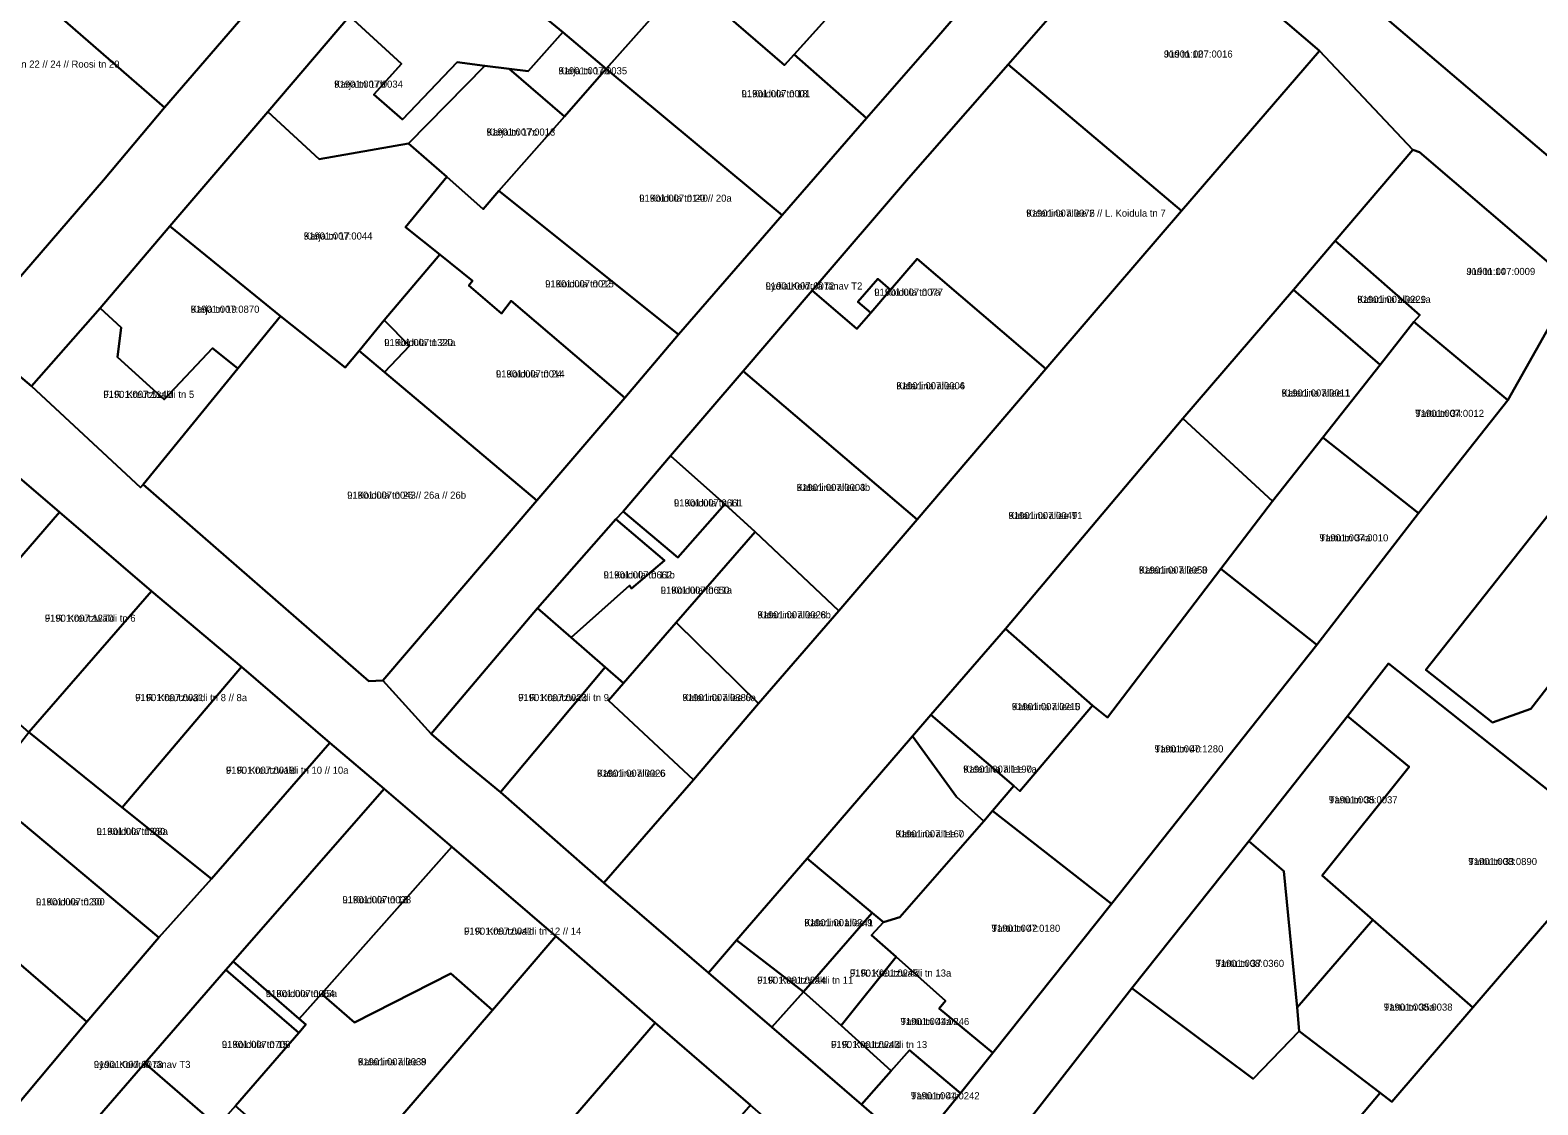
# Model space of a CAD drawing. Extents: x 675810 to 681273, y 6411190 to 6417565.
# Drawn here: x 677508.4 to 677826.5, y 6415551.1 to 6415777.9 of the extents above; entities that cross this region are included whole.
import ezdxf

# ---------------------------------------------------------------- set-up
doc = ezdxf.new("R2010")
doc.units = 0
for name, color, linetype in [('L_AADRESS', 7, 'Continuous'), ('PIIR', 7, 'Continuous'), ('TUNNUS', 7, 'Continuous')]:
    doc.layers.add(name, color=color, linetype=linetype)

msp = doc.modelspace()

# ---------------------------------------------------------------- linework, layer by layer
at = {"layer": 'PIIR'}
for points in [[(677646.67, 6415889.89), (677659.83, 6415878.49), (677628.13, 6415843.17), (677613.21, 6415825.66), (677592.59, 6415800.61), (677575.76, 6415780.87), (677558.51, 6415760.71), (677537.84, 6415736.57), (677523.1, 6415719.23), (677508.64, 6415702.82), (677495.67, 6415713.67), (677523.83, 6415746.25), (677536.7, 6415761.6), (677555.07, 6415782.89), (677568.57, 6415798.61), (677583.48, 6415815.98), (677590, 6415823.63), (677603.42, 6415839.6), (677616.31, 6415854.28)], [(677658.44, 6415802.86), (677696.86, 6415845.88), (677718.61, 6415827.15), (677669.55, 6415772.79), (677667.55, 6415770.56), (677646.64, 6415788.62), (677650.4, 6415793.16)], [(677827.43, 6415846.52), (677892.68, 6415798.34), (677892.37, 6415795.81), (677850.92, 6415745.75), (677846.94, 6415742.89), (677843.93, 6415741.95), (677839.54, 6415742.61), (677837.71, 6415743.69), (677790.48, 6415783.86), (677803.31, 6415799.07), (677793.83, 6415807.03)], [(677444.1, 6415758.98), (677420.94, 6415779.32), (677432.33, 6415792.43), (677449.54, 6415811.25), (677463.15, 6415826.36), (677481.9, 6415810.15), (677495.98, 6415797.3), (677514.66, 6415780.78), (677536.7, 6415761.6), (677523.83, 6415746.25), (677495.67, 6415713.67), (677477.14, 6415729.95)], [(677718.61, 6415827.15), (677732.71, 6415814.72), (677699.58, 6415776.22), (677684.86, 6415759.35), (677669.55, 6415772.79)], [(677613.21, 6415825.66), (677631.28, 6415809.88), (677650.4, 6415793.16), (677646.64, 6415788.62), (677629.89, 6415769.77), (677620.79, 6415777.53), (677592.59, 6415800.61)], [(677732.71, 6415814.72), (677744.3, 6415804.51), (677714.73, 6415770.67), (677693.73, 6415746.66), (677673.39, 6415722.95), (677658.8, 6415705.94), (677643.5, 6415688.11), (677633.48, 6415676.35), (677631.91, 6415674.7), (677615.44, 6415655.94), (677592.98, 6415629.43), (677582.81, 6415640.69), (677615.26, 6415678.66), (677633.81, 6415700.36), (677645.17, 6415713.67), (677667.03, 6415738.91), (677684.86, 6415759.35), (677699.58, 6415776.22)], [(677744.3, 6415804.51), (677780.41, 6415773.57), (677751.34, 6415739.78), (677714.73, 6415770.67)], [(677514.66, 6415780.78), (677533.83, 6415802.03), (677536.07, 6415800.01), (677555.07, 6415782.89), (677536.7, 6415761.6)], [(677586.72, 6415770.83), (677575.76, 6415780.87), (677592.59, 6415800.61), (677620.79, 6415777.53), (677613.42, 6415769.26), (677609.45, 6415769.75), (677604.33, 6415770.42), (677598.43, 6415771.15), (677586.9, 6415759.06), (677580.87, 6415764.37)], [(677646.64, 6415788.62), (677667.55, 6415770.56), (677669.55, 6415772.79), (677684.86, 6415759.35), (677667.03, 6415738.91), (677629.89, 6415769.77)], [(677575.76, 6415780.87), (677586.72, 6415770.83), (677580.87, 6415764.37), (677586.9, 6415759.06), (677598.43, 6415771.15), (677604.32, 6415770.43), (677588.2, 6415754.01), (677569.31, 6415750.71), (677558.51, 6415760.71)], [(677620.79, 6415777.53), (677629.89, 6415769.77), (677621.12, 6415759.72), (677609.43, 6415769.78), (677613.42, 6415769.26)], [(677751.34, 6415739.78), (677780.41, 6415773.57), (677800.15, 6415752.64), (677783.74, 6415733.44), (677774.92, 6415723.13), (677751.61, 6415695.94), (677714.14, 6415651.54), (677698.44, 6415633.45), (677694.58, 6415628.9), (677672.33, 6415603.11), (677657.41, 6415585.86), (677651.47, 6415579), (677629.42, 6415597.96), (677648.3, 6415619.73), (677662.03, 6415635.78), (677678.99, 6415655.4), (677695.52, 6415674.63), (677722.7, 6415706.45), (677732.45, 6415717.82)], [(677604.32, 6415770.43), (677609.43, 6415769.78), (677621.12, 6415759.72), (677607.26, 6415744.01), (677603.97, 6415740.16), (677596.26, 6415746.95), (677588.2, 6415754.01)], [(677629.89, 6415769.77), (677667.03, 6415738.91), (677645.17, 6415713.67), (677607.26, 6415744.01), (677621.12, 6415759.72)], [(677714.73, 6415770.67), (677751.34, 6415739.78), (677732.45, 6415717.82), (677722.7, 6415706.45), (677695.52, 6415729.64), (677689.93, 6415723.12), (677687.2, 6415725.47), (677683.03, 6415720.61), (677685.76, 6415718.27), (677682.83, 6415714.86), (677673.39, 6415722.95), (677693.73, 6415746.66)], [(677558.51, 6415760.71), (677569.31, 6415750.71), (677588.2, 6415754.01), (677596.26, 6415746.95), (677587.54, 6415736.38), (677594.79, 6415730.6), (677583.05, 6415716.73), (677577.75, 6415710.28), (677574.83, 6415706.76), (677561.2, 6415717.56), (677537.84, 6415736.57)], [(677800.15, 6415752.64), (677801.5, 6415752.2), (677830.81, 6415727.16), (677831.96, 6415720.82), (677820.17, 6415699.87), (677800.36, 6415716.35), (677801.58, 6415717.8), (677783.74, 6415733.44)], [(677596.26, 6415746.95), (677603.97, 6415740.16), (677607.26, 6415744.01), (677645.17, 6415713.67), (677633.81, 6415700.36), (677609.89, 6415720.78), (677607.79, 6415718.12), (677600.94, 6415724.01), (677601.72, 6415725), (677594.79, 6415730.6), (677587.54, 6415736.38)], [(677537.84, 6415736.57), (677561.2, 6415717.56), (677552.19, 6415706.54), (677546.8, 6415710.79), (677536.63, 6415699.99), (677526.78, 6415708.88), (677527.56, 6415715.2), (677523.1, 6415719.23)], [(677774.92, 6415723.13), (677783.74, 6415733.44), (677801.58, 6415717.8), (677800.36, 6415716.35), (677793.24, 6415707.27)], [(677594.79, 6415730.6), (677601.72, 6415725), (677600.94, 6415724.01), (677607.79, 6415718.12), (677609.89, 6415720.78), (677633.81, 6415700.36), (677615.26, 6415678.66), (677583.12, 6415705.77), (677588.39, 6415711.32), (677583.05, 6415716.73)], [(677673.39, 6415722.95), (677682.83, 6415714.86), (677685.76, 6415718.27), (677689.93, 6415723.12), (677695.52, 6415729.64), (677722.7, 6415706.45), (677695.52, 6415674.63), (677658.8, 6415705.94)], [(677687.2, 6415725.47), (677689.93, 6415723.12), (677685.76, 6415718.27), (677683.03, 6415720.61)], [(677774.92, 6415723.13), (677793.24, 6415707.27), (677781.1, 6415691.93), (677770.5, 6415678.54), (677751.61, 6415695.94)], [(677508.64, 6415702.82), (677523.1, 6415719.23), (677527.56, 6415715.2), (677526.78, 6415708.88), (677536.63, 6415699.99), (677546.8, 6415710.79), (677552.19, 6415706.54), (677532.23, 6415682.05), (677531.61, 6415681.39)], [(677561.2, 6415717.56), (677574.83, 6415706.76), (677577.75, 6415710.28), (677583.12, 6415705.77), (677615.26, 6415678.66), (677582.81, 6415640.69), (677579.84, 6415640.53), (677532.23, 6415682.05), (677552.19, 6415706.54)], [(677577.75, 6415710.28), (677583.05, 6415716.73), (677588.39, 6415711.32), (677583.12, 6415705.77)], [(677800.36, 6415716.35), (677820.17, 6415699.87), (677801.3, 6415675.96), (677781.1, 6415691.93), (677793.24, 6415707.27)], [(677658.8, 6415705.94), (677695.52, 6415674.63), (677678.99, 6415655.4), (677661.37, 6415672.02), (677654.92, 6415677.86), (677643.5, 6415688.11)], [(677735.68, 6415632.84), (677732.54, 6415635.36), (677714.14, 6415651.54), (677751.61, 6415695.94), (677770.5, 6415678.54), (677759.59, 6415664.22)], [(677802.86, 6415642.95), (677842.56, 6415693.1), (677846.73, 6415689.74), (677853.39, 6415684.52), (677855.28, 6415683.03), (677856.04, 6415682.43), (677859.93, 6415679.26), (677853.67, 6415671.09), (677866.72, 6415660.97), (677854.5, 6415645.69), (677846.09, 6415652.35), (677840.84, 6415645.75), (677836.36, 6415649.29), (677825, 6415634.7), (677816.95, 6415631.79)], [(677472.59, 6415660.83), (677498.11, 6415690.24), (677514.58, 6415676.17), (677488.89, 6415646.54)], [(677781.1, 6415691.93), (677801.3, 6415675.96), (677779.85, 6415648.18), (677759.59, 6415664.22), (677770.5, 6415678.54)], [(677643.5, 6415688.11), (677654.92, 6415677.86), (677645.06, 6415666.6), (677633.48, 6415676.35)], [(677642.18, 6415665.98), (677631.91, 6415674.7), (677633.48, 6415676.35), (677645.06, 6415666.6), (677654.92, 6415677.86), (677661.37, 6415672.02), (677644.66, 6415652.91), (677633.58, 6415640.09), (677629.67, 6415643.47), (677622.53, 6415649.71), (677634.81, 6415660.73), (677635.28, 6415660.09)], [(677533.97, 6415659.49), (677508.07, 6415629.74), (677488.89, 6415646.54), (677514.58, 6415676.17)], [(677615.44, 6415655.94), (677631.91, 6415674.7), (677642.18, 6415665.98), (677635.28, 6415660.09), (677634.81, 6415660.73), (677622.53, 6415649.71)], [(677661.37, 6415672.02), (677678.99, 6415655.4), (677662.03, 6415635.78), (677644.66, 6415652.91)], [(677779.85, 6415648.18), (677736.52, 6415593.55), (677711.43, 6415613.13), (677715.92, 6415618.4), (677717.22, 6415617.28), (677732.54, 6415635.36), (677735.68, 6415632.84), (677759.59, 6415664.22)], [(677533.97, 6415659.49), (677552.93, 6415643.54), (677527.75, 6415613.87), (677508.07, 6415629.74)], [(677615.44, 6415655.94), (677622.53, 6415649.71), (677629.67, 6415643.47), (677607.64, 6415617.12), (677599.34, 6415623.94), (677592.98, 6415629.43)], [(677630.41, 6415636.43), (677633.58, 6415640.09), (677644.66, 6415652.91), (677662.03, 6415635.78), (677648.3, 6415619.73)], [(677698.44, 6415633.45), (677714.14, 6415651.54), (677732.54, 6415635.36), (677717.22, 6415617.28), (677715.92, 6415618.4)], [(677552.93, 6415643.54), (677571.56, 6415627.5), (677546.64, 6415598.81), (677527.75, 6415613.87)], [(677648.3, 6415619.73), (677629.42, 6415597.96), (677607.64, 6415617.12), (677629.67, 6415643.47), (677633.58, 6415640.09), (677630.41, 6415636.43)], [(677795.01, 6415644.29), (677842.69, 6415606.39), (677812.82, 6415571.64), (677791.68, 6415590.18), (677780.97, 6415599.5), (677799.32, 6415622.46), (677786.34, 6415633.16)], [(677703.82, 6415616.1), (677694.58, 6415628.9), (677698.44, 6415633.45), (677715.92, 6415618.4), (677711.43, 6415613.13), (677709.58, 6415611.01)], [(677765.5, 6415606.74), (677786.34, 6415633.16), (677799.32, 6415622.46), (677780.97, 6415599.5), (677791.68, 6415590.18), (677775.7, 6415571.66), (677772.94, 6415600.44)], [(677546.64, 6415598.81), (677535.54, 6415586.39), (677506.49, 6415610.77), (677498.73, 6415617.83), (677508.07, 6415629.74), (677527.75, 6415613.87)], [(677571.56, 6415627.5), (677583.03, 6415617.83), (677551.18, 6415581.36), (677549.66, 6415579.59), (677532.56, 6415559.91), (677508.91, 6415532.58), (677473.16, 6415490.87), (677460.53, 6415498.36), (677472.49, 6415512.66), (677485.32, 6415527.43), (677497.44, 6415541.36), (677520.31, 6415568.6), (677535.54, 6415586.39), (677546.64, 6415598.81)], [(677703.82, 6415616.1), (677709.58, 6415611.01), (677691.9, 6415590.68), (677688.45, 6415589.63), (677686.03, 6415591.63), (677672.33, 6415603.11), (677694.58, 6415628.9)], [(677483.28, 6415600.55), (677498.73, 6415617.83), (677506.49, 6415610.77), (677535.54, 6415586.39), (677520.31, 6415568.6)], [(677551.18, 6415581.36), (677583.03, 6415617.83), (677597.33, 6415605.55), (677569.8, 6415574.5), (677565.12, 6415569.23)], [(677709.58, 6415611.01), (677711.43, 6415613.13), (677736.52, 6415593.55), (677711.53, 6415562.1), (677700.19, 6415571.47), (677701.53, 6415573.04), (677691.11, 6415582.33), (677685.92, 6415586.89), (677688.45, 6415589.63), (677691.9, 6415590.68)], [(677939.15, 6415495.17), (677942.44, 6415488.99), (677885.15, 6415422.56), (677876.27, 6415430.13), (677861.05, 6415443.12), (677844.04, 6415458.03), (677841.47, 6415460.28), (677849.59, 6415469.04), (677858, 6415478.15), (677841.91, 6415492.28), (677783.11, 6415541.62), (677793.25, 6415553.63), (677795.68, 6415551.77), (677812.82, 6415571.64), (677842.69, 6415606.39), (677844.64, 6415608.67), (677849.65, 6415604.71), (677905.42, 6415560.52), (677907.63, 6415562.8), (677911.67, 6415559.3), (677933.66, 6415540.22), (677949.24, 6415526.71), (677959.46, 6415517.95)], [(677597.33, 6415605.55), (677619.3, 6415586.7), (677605.9, 6415571.07), (677597.12, 6415578.84), (677576.81, 6415568.48), (677569.8, 6415574.5)], [(677740.8, 6415575.7), (677765.5, 6415606.74), (677772.94, 6415600.44), (677775.7, 6415571.66), (677776.12, 6415566.66), (677766.43, 6415556.59)], [(677459.82, 6415545.34), (677446.64, 6415556.87), (677470.86, 6415585.77), (677483.28, 6415600.55), (677520.31, 6415568.6), (677497.44, 6415541.36), (677474.87, 6415562.46)], [(677657.41, 6415585.86), (677672.33, 6415603.11), (677686.03, 6415591.63), (677671.52, 6415574.99)], [(677686.03, 6415591.63), (677688.45, 6415589.63), (677685.92, 6415586.89), (677691.11, 6415582.33), (677679.47, 6415567.82), (677671.52, 6415574.99)], [(677791.68, 6415590.18), (677812.82, 6415571.64), (677795.68, 6415551.77), (677793.25, 6415553.63), (677776.12, 6415566.66), (677775.7, 6415571.66)], [(677619.3, 6415586.7), (677640.22, 6415568.39), (677619.9, 6415544.86), (677604, 6415528.75), (677527.68, 6415439.36), (677507.74, 6415456.28), (677514.44, 6415464.15), (677541.32, 6415495.69), (677551.91, 6415508.21), (677567.84, 6415526.77), (677572.82, 6415532.42), (677579.26, 6415540.06), (677605.9, 6415571.07)], [(677651.47, 6415579), (677657.41, 6415585.86), (677671.52, 6415574.99), (677664.86, 6415567.49)], [(677551.18, 6415581.36), (677565.12, 6415569.23), (677566.5, 6415568.03), (677565.03, 6415566.32), (677549.66, 6415579.59)], [(677679.47, 6415567.82), (677691.11, 6415582.33), (677701.53, 6415573.04), (677700.19, 6415571.47), (677711.53, 6415562.1), (677704.67, 6415553.58), (677696.21, 6415560.67), (677693.92, 6415562.66), (677690.04, 6415558.3)], [(677565.03, 6415566.32), (677551.68, 6415550.86), (677547.88, 6415546.59), (677532.56, 6415559.91), (677549.66, 6415579.59)], [(677551.68, 6415550.86), (677565.03, 6415566.32), (677566.5, 6415568.03), (677565.12, 6415569.23), (677569.8, 6415574.5), (677576.81, 6415568.48), (677597.12, 6415578.84), (677605.9, 6415571.07), (677579.26, 6415540.06), (677569.45, 6415548.5), (677563.01, 6415540.96)], [(677766.43, 6415556.59), (677776.12, 6415566.66), (677793.25, 6415553.63), (677783.11, 6415541.62), (677778.77, 6415545.33), (677741.16, 6415501.73), (677708.33, 6415529.95), (677707.68, 6415533.22), (677740.8, 6415575.7)], [(677664.86, 6415567.49), (677671.52, 6415574.99), (677679.47, 6415567.82), (677690.04, 6415558.3), (677683.76, 6415551.18)], [(677619.9, 6415544.86), (677640.22, 6415568.39), (677660.36, 6415551.02), (677640.04, 6415527.46)], [(677690.04, 6415558.3), (677693.92, 6415562.66), (677696.21, 6415560.67), (677704.67, 6415553.58), (677694.9, 6415541.55), (677683.76, 6415551.18)], [(677547.88, 6415546.59), (677567.84, 6415526.77), (677551.91, 6415508.21), (677538.47, 6415519.68), (677541.45, 6415524.99), (677525.69, 6415538.85), (677514.96, 6415526.92), (677508.91, 6415532.58), (677532.56, 6415559.91)]]:
    msp.add_lwpolyline(points, close=True, dxfattribs=at)
for points in [[(677830.81, 6415727.16), (677801.5, 6415752.2), (677800.15, 6415752.64), (677780.41, 6415773.57), (677744.3, 6415804.51)], [(677790.48, 6415783.86), (677837.71, 6415743.69)], [(677842.69, 6415606.39), (677795.01, 6415644.29), (677786.34, 6415633.16), (677765.5, 6415606.74), (677740.8, 6415575.7), (677707.68, 6415533.22), (677694.9, 6415541.55), (677704.67, 6415553.58), (677711.53, 6415562.1), (677736.52, 6415593.55), (677779.85, 6415648.18), (677801.3, 6415675.96), (677820.17, 6415699.87), (677831.96, 6415720.82)], [(677495.67, 6415713.67), (677508.64, 6415702.82), (677531.61, 6415681.39), (677532.23, 6415682.05), (677579.84, 6415640.53), (677582.81, 6415640.69), (677592.98, 6415629.43), (677599.34, 6415623.94), (677607.64, 6415617.12), (677629.42, 6415597.96), (677651.47, 6415579), (677664.86, 6415567.49), (677683.76, 6415551.18), (677694.9, 6415541.55), (677707.68, 6415533.22), (677708.33, 6415529.95), (677741.16, 6415501.73), (677779.68, 6415468.8), (677806.89, 6415445.16), (677808.38, 6415444), (677821.56, 6415432.66), (677839.41, 6415417.62)], [(677842.56, 6415693.1), (677802.86, 6415642.95), (677816.95, 6415631.79), (677825, 6415634.7), (677836.36, 6415649.29)], [(677841.37, 6415395.02), (677809, 6415423.1), (677797.76, 6415432.58), (677774.64, 6415452.34), (677734.01, 6415487.03), (677713.91, 6415504.57), (677696.92, 6415519.61), (677686.05, 6415528.82), (677660.36, 6415551.02), (677640.22, 6415568.39), (677619.3, 6415586.7), (677597.33, 6415605.55), (677583.03, 6415617.83), (677571.56, 6415627.5), (677552.93, 6415643.54), (677533.97, 6415659.49), (677514.58, 6415676.17), (677498.11, 6415690.24)]]:
    msp.add_lwpolyline(points, dxfattribs=at)

# ---------------------------------------------------------------- texts
at = {"layer": 'L_AADRESS'}
for s, p in [('Jüri tn 12', (677747.6, 6415772.15)), ('F. R. Kreutzwaldi tn 1 // Karja tn 22 // 24 // Roosi tn 29', (677479.28, 6415770.02)), ('Karja tn 17d', (677619.83, 6415768.62)), ('Karja tn 17b', (677572.51, 6415765.79)), ('L. Koidula tn 18', (677658.47, 6415763.77)), ('Karja tn 17c', (677604.66, 6415755.68)), ('L. Koidula tn 20 // 20a', (677636.88, 6415741.72)), ('Katariina allee 2 // L. Koidula tn 7', (677718.54, 6415738.56)), ('Karja tn 17', (677566.09, 6415733.74)), ('Jüri tn 14', (677811.45, 6415726.26)), ('L. Koidula tn 22', (677617.02, 6415723.65)), ('Lydia Koidula tänav T2', (677663.55, 6415723.19)), ('L. Koidula tn 7a', (677686.48, 6415721.87)), ('Katariina allee 1a', (677788.4, 6415720.36)), ('Karja tn 19', (677542.23, 6415718.28)), ('L. Koidula tn 24a', (677583.07, 6415711.26)), ('L. Koidula tn 24', (677606.64, 6415704.63)), ('Katariina allee 4', (677691.14, 6415702.13)), ('F. R. Kreutzwaldi tn 5', (677523.8, 6415700.31)), ('Katariina allee 1', (677772.43, 6415700.6)), ('Tartu tn 34', (677800.64, 6415696.3)), ('L. Koidula tn 26 // 26a // 26b', (677575.24, 6415679.04)), ('Katariina allee 4b', (677670.11, 6415680.67)), ('L. Koidula tn 11', (677644.2, 6415677.4)), ('Katariina allee T1', (677714.79, 6415674.74)), ('Tartu tn 34a', (677780.45, 6415670.03)), ('Katariina allee 3', (677742.32, 6415663.24)), ('L. Koidula tn 11b', (677629.35, 6415662.21)), ('L. Koidula tn 11a', (677641.41, 6415658.98)), ('F. R. Kreutzwaldi tn 6', (677511.43, 6415653.07)), ('Katariina allee 6b', (677661.82, 6415653.79)), ('F. R. Kreutzwaldi tn 8 // 8a', (677530.5, 6415636.31)), ('F. R. Kreutzwaldi tn 9', (677611.32, 6415636.31)), ('Katariina allee 6a', (677646.01, 6415636.32)), ('Katariina allee 5', (677715.5, 6415634.41)), ('Tartu tn 40', (677745.64, 6415625.48)), ('Katariina allee 7a', (677705.25, 6415621.21)), ('F. R. Kreutzwaldi tn 10 // 10a', (677549.66, 6415620.98)), ('Katariina allee 6', (677627.97, 6415620.34)), ('Tartu tn 35', (677782.41, 6415614.74)), ('L. Koidula tn 28a', (677522.37, 6415608.07)), ('Katariina allee 7', (677690.95, 6415607.55)), ('Tartu tn 33', (677811.83, 6415601.71)), ('L. Koidula tn 30', (677509.59, 6415593.21)), ('L. Koidula tn 13', (677574.25, 6415593.65)), ('F. R. Kreutzwaldi tn 12 // 14', (677599.91, 6415587.02)), ('Katariina allee 9', (677671.72, 6415588.81)), ('Tartu tn 42', (677711.22, 6415587.62)), ('Tartu tn 37', (677758.46, 6415580.21)), ('F. R. Kreutzwaldi tn 11', (677661.75, 6415576.67)), ('F. R. Kreutzwaldi tn 13a', (677681.32, 6415578.17)), ('L. Koidula tn 15a', (677558.07, 6415573.84)), ('Tartu tn 35a', (677794, 6415570.98)), ('Tartu tn 44a', (677692.01, 6415567.95)), ('L. Koidula tn 15', (677548.8, 6415563.11)), ('F. R. Kreutzwaldi tn 13', (677677.35, 6415563.08)), ('Lydia Koidula tänav T3', (677521.78, 6415558.88)), ('Katariina allee 8', (677577.51, 6415559.45)), ('Tartu tn 44', (677694.21, 6415552.27))]:
    msp.add_text(s, height=1.5, dxfattribs=at).set_placement(p)
at = {"layer": 'TUNNUS'}
for s, p in [('91901:007:0016', (677747.6, 6415772.15)), ('91901:007:0035', (677619.83, 6415768.62)), ('91901:007:0034', (677572.51, 6415765.79)), ('91901:007:0001', (677658.47, 6415763.77)), ('91901:007:0013', (677604.66, 6415755.68)), ('91901:007:0140', (677636.88, 6415741.72)), ('91901:007:0076', (677718.54, 6415738.56)), ('91901:007:0044', (677566.09, 6415733.74)), ('91901:007:0009', (677811.45, 6415726.26)), ('91901:007:0015', (677617.02, 6415723.65)), ('91901:007:0072', (677663.55, 6415723.19)), ('91901:007:0077', (677686.48, 6415721.87)), ('91901:001:0229', (677788.4, 6415720.36)), ('91901:007:0870', (677542.23, 6415718.28)), ('91901:007:1320', (677583.07, 6415711.26)), ('91901:007:0014', (677606.64, 6415704.63)), ('91901:007:0006', (677691.14, 6415702.13)), ('91901:007:1140', (677523.8, 6415700.31)), ('91901:007:0011', (677772.43, 6415700.6)), ('91901:007:0012', (677800.64, 6415696.3)), ('91901:007:0043', (677575.24, 6415679.04)), ('91901:007:0003', (677670.11, 6415680.67)), ('91901:007:0661', (677644.2, 6415677.4)), ('91901:007:0049', (677714.79, 6415674.74)), ('91901:007:0010', (677780.45, 6415670.03)), ('91901:007:0050', (677742.32, 6415663.24)), ('91901:007:0662', (677629.35, 6415662.21)), ('91901:007:0650', (677641.41, 6415658.98)), ('91901:007:1270', (677511.43, 6415653.07)), ('91901:007:0028', (677661.82, 6415653.79)), ('91901:007:0031', (677530.5, 6415636.31)), ('91901:007:0023', (677611.32, 6415636.31)), ('91901:007:0380', (677646.01, 6415636.32)), ('91901:007:0210', (677715.5, 6415634.41)), ('91901:007:1280', (677745.64, 6415625.48)), ('91901:007:1190', (677705.25, 6415621.21)), ('91901:007:0019', (677549.66, 6415620.98)), ('91901:007:0026', (677627.97, 6415620.34)), ('91901:008:0037', (677782.41, 6415614.74)), ('91901:007:1260', (677522.37, 6415608.07)), ('91901:007:1160', (677690.95, 6415607.55)), ('91901:008:0890', (677811.83, 6415601.71)), ('91901:007:0200', (677509.59, 6415593.21)), ('91901:007:0038', (677574.25, 6415593.65)), ('91901:007:0041', (677599.91, 6415587.02)), ('91901:001:0241', (677671.72, 6415588.81)), ('91901:007:0180', (677711.22, 6415587.62)), ('91901:008:0360', (677758.46, 6415580.21)), ('91901:001:0244', (677661.75, 6415576.67)), ('91901:001:0245', (677681.32, 6415578.17)), ('91901:007:0064', (677558.07, 6415573.84)), ('91901:008:0038', (677794, 6415570.98)), ('91901:001:0246', (677692.01, 6415567.95)), ('91901:007:0700', (677548.8, 6415563.11)), ('91901:001:0243', (677677.35, 6415563.08)), ('91901:007:0073', (677521.78, 6415558.88)), ('91901:007:0039', (677577.51, 6415559.45)), ('91901:001:0242', (677694.21, 6415552.27))]:
    msp.add_text(s, height=1.5, dxfattribs=at).set_placement(p)

doc.saveas('drawing.dxf')
